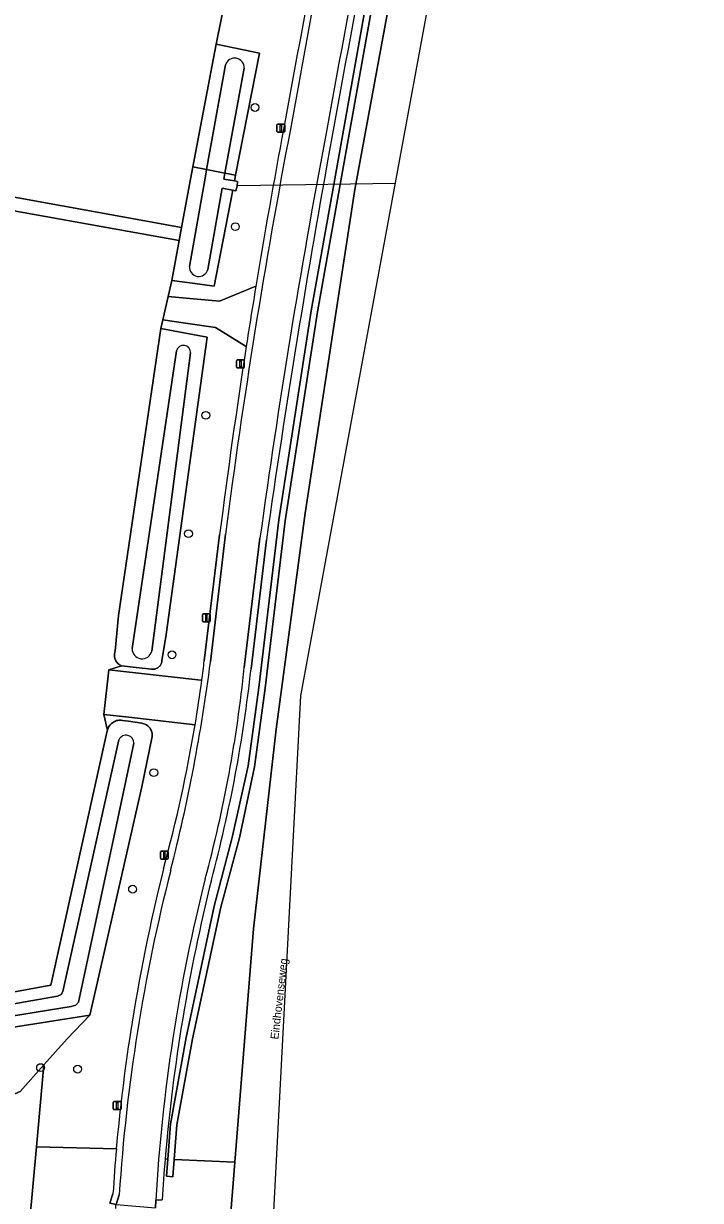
# Model space of a CAD drawing. Extents: x 161385 to 162589, y 388479 to 389756.
# Drawn here: x 162498.2 to 162582.9, y 389100.4 to 389247.5 of the extents above; entities that cross this region are included whole.
import ezdxf

# ---------------------------------------------------------------- set-up
doc = ezdxf.new("R2010")
doc.units = 0
for name, color, linetype in [('IMGEO_Berm_groen', 7, 'Continuous'), ('IMGEO_Berm_open', 7, 'Continuous'), ('IMGEO_Boom', 7, 'Continuous'), ('IMGEO_Bouwland', 7, 'Continuous'), ('IMGEO_Duiker', 7, 'Continuous'), ('IMGEO_Erf', 7, 'Continuous'), ('IMGEO_Fietspad_gesloten', 7, 'Continuous'), ('IMGEO_Grasland_overig', 7, 'Continuous'), ('IMGEO_Groenvoorziening', 7, 'Continuous'), ('IMGEO_Haag', 7, 'Continuous'), ('IMGEO_Lichtmast', 7, 'Continuous'), ('IMGEO_Loofbos', 7, 'Continuous'), ('IMGEO_Oever', 7, 'Continuous'), ('IMGEO_Openbare_ruimte_label', 7, 'Continuous'), ('IMGEO_Rijbaan_lokaal_open', 7, 'Continuous'), ('IMGEO_Rijbaan_regionaal_gesloten', 7, 'Continuous'), ('IMGEO_Verkeerseiland_groen', 7, 'Continuous'), ('IMGEO_Waterloop', 7, 'Continuous')]:
    doc.layers.add(name, color=color, linetype=linetype)

msp = doc.modelspace()

# ---------------------------------------------------------------- linework, layer by layer
at = {"layer": 'IMGEO_Berm_groen'}
for points in [[(162515.95, 389105.58), (162516.29, 389105.55), (162516.61, 389109.92), (162518.58, 389120.76), (162522.08, 389137.16), (162524.35, 389145.75), (162526.33, 389154.68), (162527.69, 389164.49), (162530.19, 389185.45), (162534.23, 389211.56), (162537.05, 389227.35), (162541.11, 389250.07)], [(162541.89, 389249.93), (162537.86, 389227.36), (162535.02, 389211.43), (162530.98, 389185.34), (162528.48, 389164.39), (162527.13, 389154.56), (162525.27, 389145.69), (162522.92, 389137.04), (162519.37, 389120.59), (162517.41, 389109.82), (162517.09, 389105.51), (162524.67, 389105.18), (162527.01, 389134.31), (162529.83, 389159.28), (162533.46, 389186.29), (162539.7, 389226.74), (162539.82, 389227.39), (162543.99, 389250)], [(162528.63, 389182.97), (162526.7, 389166.82)]]:
    msp.add_lwpolyline(points, dxfattribs=at)
for centre, radius, start, end in [((165430.74, 388709.98), 2940.85, 168.58464, 169.75115), ((163865.58, 388991.1), 1350.65, 169.67296, 171.83337), ((162353.56, 389185.73), 174.17, 344.9225, 353.7664), ((162738.94, 389086.46), 223.81, 166.0456, 175.0996)]:
    msp.add_arc(centre, radius, start, end, dxfattribs=at)
at = {"layer": 'IMGEO_Berm_open'}
for points in [[(162522.77, 389183.57), (162520.84, 389167.84)], [(162521.64, 389167.68), (162523.51, 389183.65)], [(162527.82, 389183.14), (162525.85, 389166.98)], [(162526.7, 389166.82), (162528.63, 389182.97)], [(162509.42, 389101.22), (162509.03, 389100.04), (162509.81, 389099.87), (162510.21, 389101.09)], [(162514.77, 389100.42), (162515.57, 389100.47)]]:
    msp.add_lwpolyline(points, dxfattribs=at)
for centre, radius, start, end in [((166558.63, 388497.78), 4094.64, 168.80107, 169.63564), ((165549.5, 388690.44), 3066.49, 168.66946, 169.78423), ((165801.81, 388642.75), 3318.76, 168.71278, 169.74959), ((165430.74, 388709.98), 2940.85, 168.58464, 169.75115), ((163380.67, 389072.21), 864.38, 169.19171, 172.59244), ((163383.98, 389073.51), 868.22, 169.3186, 170.64564), ((163529.83, 389045.24), 1011.46, 169.28293, 172.16365), ((163865.58, 388991.1), 1350.65, 169.67296, 171.83337), ((163357.31, 389077.87), 841.2, 170.64276, 171.16184), ((163371.45, 389075.44), 855.54, 171.14652, 172.73911), ((162300.78, 389196.46), 222.72, 345.7416, 352.5741), ((162337.16, 389189.91), 185.01, 352.3841, 353.1464), ((162361.08, 389183.83), 165.63, 344.8832, 354.1641), ((162353.56, 389185.73), 174.17, 344.9225, 353.7664), ((162340.51, 389189.55), 181.64, 350.5844, 352.3561), ((162342.8, 389189.17), 179.31, 344.6948, 350.5867), ((162731.04, 389086.79), 221.29, 165.6569, 176.2937), ((162735.65, 389086.74), 226.69, 165.9351, 171.2124), ((162729.97, 389087.83), 215.56, 165.8212, 176.6524), ((162738.94, 389086.46), 223.81, 166.0456, 175.0996), ((162735.42, 389086.75), 226.47, 171.2044, 174.9096), ((162735.89, 389086.69), 226.93, 174.9056, 176.3297), ((162733.03, 389086.87), 217.88, 175.074, 176.4218)]:
    msp.add_arc(centre, radius, start, end, dxfattribs=at)
at = {"layer": 'IMGEO_Boom'}
for centre in [(162527.19, 389236.99), (162524.74, 389222.09), (162521.05, 389198.52), (162518.88, 389183.72), (162516.81, 389168.58), (162514.53, 389153.85), (162511.88, 389139.28), (162500.37, 389116.98), (162505, 389116.79)]:
    msp.add_circle(centre, 0.489, dxfattribs=at)
at = {"layer": 'IMGEO_Bouwland'}
msp.add_lwpolyline([(162365.69, 389304.53), (162378.86, 389305.21), (162381.46, 389305.34), (162386.58, 389305.3), (162392.87, 389304.96), (162400.44, 389304.98), (162407.4, 389305.15), (162413.86, 389305.32), (162420.57, 389304.98), (162428.12, 389304.98), (162438.44, 389304.9), (162451.55, 389304.33), (162457.77, 389232.9), (162518.01, 389222.01), (162519.26, 389228.69), (162519.43, 389229.57), (162522.32, 389244.9), (162523.68, 389251.54), (162528.42, 389274.72), (162532.91, 389298.77), (162450.78, 389315.08), (162458.14, 389368.42)], dxfattribs=at)
at = {"layer": 'IMGEO_Duiker'}
msp.add_lwpolyline([(162525.04, 389227.23), (162544.78, 389227.55)], dxfattribs=at)
at = {"layer": 'IMGEO_Erf'}
msp.add_lwpolyline([(162464.29, 389120.39), (162501.65, 389127.29), (162508.71, 389159.07), (162508.73, 389159.13), (162508.3, 389161.12), (162508.89, 389166.7), (162510.49, 389167.21), (162510.46, 389167.22), (162510.35, 389167.27), (162510.24, 389167.34), (162510.14, 389167.42), (162510.04, 389167.51), (162509.95, 389167.6), (162509.87, 389167.7), (162509.8, 389167.81), (162509.74, 389167.92), (162509.69, 389168.04), (162509.66, 389168.17), (162509.63, 389168.29), (162509.61, 389168.42), (162509.61, 389168.55), (162509.62, 389168.68), (162509.64, 389168.81), (162509.67, 389168.93), (162509.71, 389169.06), (162510.13, 389173.5), (162515.4, 389209.36), (162515.66, 389210.47), (162516.35, 389213.36), (162516.77, 389215.38), (162517.7, 389220.36), (162461.43, 389230.46)], dxfattribs=at)
at = {"layer": 'IMGEO_Fietspad_gesloten'}
for points in [[(162523.51, 389183.65), (162521.64, 389167.68)], [(162525.85, 389166.98), (162527.82, 389183.14)], [(162510.21, 389101.09), (162509.81, 389099.87), (162514.74, 389099.44), (162514.77, 389100.42)]]:
    msp.add_lwpolyline(points, dxfattribs=at)
for centre, radius, start, end in [((165549.5, 388690.44), 3066.49, 168.66946, 169.78423), ((165801.81, 388642.75), 3318.76, 168.71278, 169.74959), ((163380.67, 389072.21), 864.38, 169.19171, 172.59244), ((163529.83, 389045.24), 1011.46, 169.28293, 172.16365), ((162300.78, 389196.46), 222.72, 345.7416, 352.5741), ((162361.08, 389183.83), 165.63, 344.8832, 354.1641), ((162731.04, 389086.79), 221.29, 165.6569, 176.2937), ((162729.97, 389087.83), 215.56, 165.8212, 176.6524)]:
    msp.add_arc(centre, radius, start, end, dxfattribs=at)
at = {"layer": 'IMGEO_Grasland_overig'}
msp.add_lwpolyline([(162452.04, 389250), (162454.75, 389231.66), (162461.43, 389230.46), (162517.7, 389220.36), (162518.01, 389222.01), (162457.77, 389232.9), (162451.55, 389304.33)], dxfattribs=at)
at = {"layer": 'IMGEO_Groenvoorziening'}
for points in [[(162523.68, 389251.54), (162522.32, 389244.9), (162524.75, 389244.4), (162527.74, 389243.79), (162524.77, 389228.54), (162524.66, 389228.01), (162524.63, 389227.82), (162525, 389227.76), (162524.96, 389227.16), (162524.81, 389226.56), (162524.4, 389226.64), (162524.36, 389226.43), (162522.07, 389214.66), (162519.37, 389215.03), (162516.77, 389215.38), (162516.35, 389213.36), (162519.05, 389213.13), (162522.77, 389212.8), (162527.3, 389214.64)], [(162541.11, 389250.07), (162537.05, 389227.35), (162534.23, 389211.56), (162530.19, 389185.45), (162527.69, 389164.49), (162526.33, 389154.68), (162524.35, 389145.75), (162522.08, 389137.16), (162518.58, 389120.76), (162516.61, 389109.92), (162516.29, 389105.55), (162516.13, 389103.4), (162516.93, 389103.34), (162517.09, 389105.51), (162517.41, 389109.82), (162519.37, 389120.59), (162522.92, 389137.04), (162525.27, 389145.69), (162527.13, 389154.56), (162528.48, 389164.39), (162530.98, 389185.34), (162535.02, 389211.43), (162537.86, 389227.36), (162541.89, 389249.93)], [(162526.1, 389207.11), (162522.25, 389209.48), (162518.52, 389210.04), (162515.66, 389210.47), (162515.4, 389209.36), (162518.31, 389208.83), (162521.21, 389208.29), (162516.09, 389171.11), (162515.54, 389167.83), (162515.53, 389167.76), (162515.52, 389167.66), (162515.49, 389167.57), (162515.46, 389167.47), (162515.42, 389167.38), (162515.37, 389167.29), (162515.31, 389167.21), (162515.25, 389167.14), (162515.18, 389167.06), (162515.1, 389167), (162515.02, 389166.94), (162514.94, 389166.89), (162514.85, 389166.85), (162514.75, 389166.81), (162514.65, 389166.79), (162514.55, 389166.77), (162514.46, 389166.77), (162514.36, 389166.77), (162514.26, 389166.78), (162512.33, 389166.99), (162510.49, 389167.21), (162508.89, 389166.7), (162512.24, 389166.33), (162520.41, 389165.4), (162520.53, 389165.39)], [(162520.84, 389167.84), (162522.77, 389183.57)], [(162519.7, 389159.84), (162511.42, 389160.77), (162508.3, 389161.12), (162508.73, 389159.13), (162508.76, 389159.27), (162508.82, 389159.41), (162508.88, 389159.54), (162508.95, 389159.67), (162509.04, 389159.79), (162509.14, 389159.9), (162509.24, 389160), (162509.36, 389160.09), (162509.48, 389160.17), (162509.61, 389160.24), (162509.74, 389160.3), (162509.88, 389160.35), (162510.02, 389160.38), (162510.17, 389160.4), (162510.31, 389160.41), (162510.46, 389160.4), (162510.6, 389160.38), (162511.35, 389160.28), (162513.04, 389160.03), (162513.16, 389160.01), (162513.29, 389159.97), (162513.42, 389159.92), (162513.55, 389159.86), (162513.66, 389159.79), (162513.77, 389159.71), (162513.88, 389159.62), (162513.97, 389159.52), (162514.06, 389159.41), (162514.13, 389159.3), (162514.2, 389159.17), (162514.25, 389159.05), (162514.29, 389158.92), (162514.32, 389158.79), (162514.34, 389158.65), (162514.35, 389158.51), (162514.34, 389158.38), (162513.03, 389152.06), (162507.36, 389127.14), (162506.53, 389123.52), (162503.71, 389120.57), (162500.78, 389117.31), (162499.85, 389107.07), (162509.85, 389106.84)], [(162509.85, 389106.84), (162499.85, 389107.07), (162498.96, 389097.09), (162500, 389096.93), (162503.05, 389096.67), (162504.14, 389096.81), (162506.22, 389096.8)], [(162509.79, 389099.38), (162509.8, 389099.73), (162509.81, 389099.87), (162509.03, 389100.04), (162509.42, 389101.22)]]:
    msp.add_lwpolyline(points, dxfattribs=at)
msp.add_lwpolyline([(162500.78, 389117.31), (162497.83, 389114.01), (162491.39, 389111.2), (162486.6, 389105.87), (162485.73, 389102.19), (162485.57, 389100.86), (162490.55, 389099.01), (162491.45, 389098.72), (162492.35, 389098.43), (162497.21, 389097.36), (162498.96, 389097.09), (162499.85, 389107.07)], close=True, dxfattribs=at)
for centre, radius, start, end in [((166558.63, 388497.78), 4094.64, 168.80107, 169.63564), ((163383.98, 389073.51), 868.22, 169.3186, 170.64564), ((163371.45, 389075.44), 855.54, 171.14652, 172.73911), ((162337.16, 389189.91), 185.01, 352.3841, 353.1464), ((162342.8, 389189.17), 179.31, 344.6948, 350.5867), ((162735.65, 389086.74), 226.69, 165.9351, 171.2124), ((162735.42, 389086.75), 226.47, 171.2044, 174.9096), ((162735.89, 389086.69), 226.93, 174.9056, 176.3297)]:
    msp.add_arc(centre, radius, start, end, dxfattribs=at)
at = {"layer": 'IMGEO_Haag'}
msp.add_lwpolyline([(162541.11, 389250.07), (162537.05, 389227.35), (162534.23, 389211.56), (162530.19, 389185.45), (162527.69, 389164.49), (162526.33, 389154.68), (162524.35, 389145.75), (162522.08, 389137.16), (162518.58, 389120.76), (162516.61, 389109.92), (162516.29, 389105.55), (162516.13, 389103.4), (162516.93, 389103.34), (162517.09, 389105.51), (162517.41, 389109.82), (162519.37, 389120.59), (162522.92, 389137.04), (162525.27, 389145.69), (162527.13, 389154.56), (162528.48, 389164.39), (162530.98, 389185.34), (162535.02, 389211.43), (162537.86, 389227.36), (162541.89, 389249.93)], dxfattribs=at)
at = {"layer": 'IMGEO_Lichtmast'}
for p, q in [((162529.94, 389234.01), (162529.94, 389234.81)), ((162529.94, 389234.81), (162529.94, 389234.01)), ((162530.04, 389234.91), (162530.83, 389234.91)), ((162530.83, 389234.91), (162530.04, 389234.91)), ((162530.83, 389233.91), (162530.04, 389233.91)), ((162530.04, 389233.91), (162530.83, 389233.91)), ((162530.93, 389234.81), (162530.93, 389234.01)), ((162530.93, 389234.01), (162530.93, 389234.81)), ((162524.88, 389204.54), (162524.88, 389205.34)), ((162524.88, 389205.34), (162524.88, 389204.54)), ((162524.98, 389205.44), (162525.76, 389205.44)), ((162525.76, 389205.44), (162524.98, 389205.44)), ((162525.76, 389204.44), (162524.98, 389204.44)), ((162524.98, 389204.44), (162525.76, 389204.44)), ((162525.86, 389205.34), (162525.86, 389204.54)), ((162525.86, 389204.54), (162525.86, 389205.34)), ((162520.61, 389172.8), (162520.61, 389173.6)), ((162520.61, 389173.6), (162520.61, 389172.8)), ((162520.71, 389173.7), (162521.5, 389173.7)), ((162521.5, 389173.7), (162520.71, 389173.7)), ((162521.6, 389173.6), (162521.6, 389172.8)), ((162521.6, 389172.8), (162521.6, 389173.6)), ((162521.5, 389172.7), (162520.71, 389172.7)), ((162520.71, 389172.7), (162521.5, 389172.7)), ((162515.36, 389143.14), (162515.36, 389143.94)), ((162515.36, 389143.94), (162515.36, 389143.14)), ((162515.46, 389144.04), (162516.25, 389144.04)), ((162516.25, 389144.04), (162515.46, 389144.04)), ((162516.35, 389143.94), (162516.35, 389143.14)), ((162516.35, 389143.14), (162516.35, 389143.94)), ((162516.25, 389143.04), (162515.46, 389143.04)), ((162515.46, 389143.04), (162516.25, 389143.04)), ((162509.46, 389111.83), (162509.46, 389112.63)), ((162509.46, 389112.63), (162509.46, 389111.83)), ((162509.56, 389112.73), (162510.35, 389112.73)), ((162510.35, 389112.73), (162509.56, 389112.73)), ((162510.35, 389111.73), (162509.56, 389111.73)), ((162509.56, 389111.73), (162510.35, 389111.73)), ((162510.45, 389112.63), (162510.45, 389111.83)), ((162510.45, 389111.83), (162510.45, 389112.63))]:
    msp.add_line(p, q, dxfattribs=at)
for points in [[(162530.36, 389234.78), (162530.51, 389234.78), (162530.51, 389234.03), (162530.36, 389234.03), (162530.36, 389234.78)], [(162525.29, 389205.31), (162525.45, 389205.31), (162525.45, 389204.56), (162525.29, 389204.56), (162525.29, 389205.31)], [(162521.03, 389173.57), (162521.18, 389173.57), (162521.18, 389172.82), (162521.03, 389172.82), (162521.03, 389173.57)], [(162515.78, 389143.92), (162515.93, 389143.92), (162515.93, 389143.17), (162515.78, 389143.17), (162515.78, 389143.92)], [(162509.88, 389112.6), (162510.03, 389112.6), (162510.03, 389111.85), (162509.88, 389111.85), (162509.88, 389112.6)]]:
    msp.add_lwpolyline(points, dxfattribs=at)
for centre, start, end in [((162530.04, 389234.81), 90, 180), ((162530.04, 389234.81), 90, 180), ((162530.04, 389234.01), 180, 270), ((162530.04, 389234.01), 180, 270), ((162530.83, 389234.81), 0, 90), ((162530.83, 389234.81), 360, 90), ((162530.83, 389234.01), 270, 0), ((162530.83, 389234.01), 270, 0), ((162524.98, 389205.34), 90, 180), ((162524.98, 389205.34), 90, 180), ((162524.98, 389204.54), 180, 270), ((162524.98, 389204.54), 180, 270), ((162525.76, 389205.34), 0, 90), ((162525.76, 389205.34), 360, 90), ((162525.76, 389204.54), 270, 0), ((162525.76, 389204.54), 270, 0), ((162520.71, 389173.6), 90, 180), ((162520.71, 389173.6), 90, 180), ((162521.5, 389173.6), 0, 90), ((162521.5, 389173.6), 360, 90), ((162520.71, 389172.8), 180, 270), ((162520.71, 389172.8), 180, 270), ((162521.5, 389172.8), 270, 0), ((162521.5, 389172.8), 270, 0), ((162515.46, 389143.94), 90, 180), ((162515.46, 389143.94), 90, 180), ((162516.25, 389143.94), 0, 90), ((162516.25, 389143.94), 360, 90), ((162515.46, 389143.14), 180, 270), ((162515.46, 389143.14), 180, 270), ((162516.25, 389143.14), 270, 0), ((162516.25, 389143.14), 270, 0), ((162509.56, 389112.63), 90, 180), ((162509.56, 389112.63), 90, 180), ((162509.56, 389111.83), 180, 270), ((162509.56, 389111.83), 180, 270), ((162510.35, 389112.63), 0, 90), ((162510.35, 389112.63), 360, 90), ((162510.35, 389111.83), 270, 0), ((162510.35, 389111.83), 270, 0)]:
    msp.add_arc(centre, 0.1, start, end, dxfattribs=at)
at = {"layer": 'IMGEO_Loofbos'}
msp.add_lwpolyline([(162503.71, 389120.57), (162506.53, 389123.52), (162501.24, 389122.69), (162477.09, 389118.89), (162464.99, 389116.84), (162464.67, 389118.46), (162464.29, 389120.39), (162462.23, 389120), (162462.59, 389118.05), (162462.88, 389116.48), (162442.25, 389112.99), (162443.13, 389111.82), (162447.72, 389111.92), (162452.3, 389111.62), (162456.83, 389110.91), (162461.29, 389109.79), (162465.62, 389108.29), (162485.57, 389100.86), (162485.73, 389102.19), (162486.6, 389105.87), (162491.39, 389111.2), (162497.83, 389114.01), (162500.78, 389117.31)], close=True, dxfattribs=at)
at = {"layer": 'IMGEO_Oever'}
for points in [[(162525.84, 389241.91), (162523.43, 389228.8), (162524.77, 389228.54), (162527.74, 389243.79), (162524.75, 389244.4), (162522.32, 389244.9), (162519.43, 389229.57)], [(162519.43, 389229.57), (162521.14, 389229.24), (162523.5, 389242.32)], [(162521.14, 389229.24), (162519.43, 389229.57), (162519.26, 389228.69), (162518.01, 389222.01), (162517.7, 389220.36), (162516.77, 389215.38), (162519.37, 389215.03), (162522.07, 389214.66), (162524.36, 389226.43), (162524.4, 389226.64), (162523.08, 389226.89), (162521.31, 389216.74)], [(162519, 389217.13), (162520.99, 389228.41), (162521.14, 389229.24)], [(162511.83, 389169.36), (162517.39, 389206.56)], [(162519.12, 389206.32), (162514.28, 389169.04)], [(162477.09, 389118.89), (162501.24, 389122.69), (162506.53, 389123.52), (162507.36, 389127.14), (162513.03, 389152.06), (162514.34, 389158.38), (162514.35, 389158.51), (162514.34, 389158.65), (162514.32, 389158.79), (162514.29, 389158.92), (162514.25, 389159.05), (162514.2, 389159.17), (162514.13, 389159.3), (162514.06, 389159.41), (162513.97, 389159.52), (162513.88, 389159.62), (162513.77, 389159.71), (162513.66, 389159.79), (162513.55, 389159.86), (162513.42, 389159.92), (162513.29, 389159.97), (162513.16, 389160.01), (162513.04, 389160.03), (162511.35, 389160.28), (162510.6, 389160.38), (162510.46, 389160.4), (162510.31, 389160.41), (162510.17, 389160.4), (162510.02, 389160.38), (162509.88, 389160.35), (162509.74, 389160.3), (162509.61, 389160.24), (162509.48, 389160.17), (162509.36, 389160.09), (162509.24, 389160), (162509.14, 389159.9), (162509.04, 389159.79), (162508.95, 389159.67), (162508.88, 389159.54), (162508.82, 389159.41), (162508.76, 389159.27), (162508.73, 389159.13), (162508.71, 389159.07), (162501.65, 389127.29), (162464.29, 389120.39)], [(162465.56, 389119.47), (162502.48, 389125.91), (162502.94, 389126.12), (162503.14, 389126.51), (162510.18, 389157.95)], [(162512.05, 389157.52), (162509.73, 389146.76), (162505.11, 389125.18), (162504.78, 389124.79), (162504.18, 389124.6), (162488.97, 389122.14), (162465.85, 389118.02), (162465.56, 389119.47)]]:
    msp.add_lwpolyline(points, dxfattribs=at)
for points in [[(162524.77, 389228.54), (162523.43, 389228.8), (162523.28, 389228.03), (162524.63, 389227.82), (162524.66, 389228.01)], [(162521.21, 389208.29), (162518.31, 389208.83), (162515.4, 389209.36), (162510.13, 389173.5), (162509.71, 389169.06), (162509.67, 389168.93), (162509.64, 389168.81), (162509.62, 389168.68), (162509.61, 389168.55), (162509.61, 389168.42), (162509.63, 389168.29), (162509.66, 389168.17), (162509.69, 389168.04), (162509.74, 389167.92), (162509.8, 389167.81), (162509.87, 389167.7), (162509.95, 389167.6), (162510.04, 389167.51), (162510.14, 389167.42), (162510.24, 389167.34), (162510.35, 389167.27), (162510.46, 389167.22), (162510.49, 389167.21), (162512.33, 389166.99), (162514.26, 389166.78), (162514.36, 389166.77), (162514.46, 389166.77), (162514.55, 389166.77), (162514.65, 389166.79), (162514.75, 389166.81), (162514.85, 389166.85), (162514.94, 389166.89), (162515.02, 389166.94), (162515.1, 389167), (162515.18, 389167.06), (162515.25, 389167.14), (162515.31, 389167.21), (162515.37, 389167.29), (162515.42, 389167.38), (162515.46, 389167.47), (162515.49, 389167.57), (162515.52, 389167.66), (162515.53, 389167.76), (162515.54, 389167.83), (162516.09, 389171.11)]]:
    msp.add_lwpolyline(points, close=True, dxfattribs=at)
for centre, radius, start, end in [((162524.65, 389241.96), 1.2, 357.2372, 162.8474), ((162520.17, 389217.04), 1.17, 175.6482, 345.1451), ((162518.24, 389206.38), 0.875, 355.8359, 168.0896), ((162513.07, 389169.32), 1.24, 177.9953, 346.9475), ((162511.07, 389157.56), 0.976, 357.8213, 156.2073)]:
    msp.add_arc(centre, radius, start, end, dxfattribs=at)
at = {"layer": 'IMGEO_Rijbaan_lokaal_open'}
for points in [[(162527.3, 389214.64), (162522.77, 389212.8), (162519.05, 389213.13), (162516.35, 389213.36), (162515.66, 389210.47), (162518.52, 389210.04), (162522.25, 389209.48), (162526.1, 389207.11)], [(162520.53, 389165.39), (162520.41, 389165.4), (162512.24, 389166.33), (162508.89, 389166.7), (162508.3, 389161.12), (162511.42, 389160.77), (162519.7, 389159.84)]]:
    msp.add_lwpolyline(points, dxfattribs=at)
for centre, radius, start, end in [((163357.31, 389077.87), 841.2, 170.64276, 171.16184), ((162340.51, 389189.55), 181.64, 350.5844, 352.3561)]:
    msp.add_arc(centre, radius, start, end, dxfattribs=at)
at = {"layer": 'IMGEO_Rijbaan_regionaal_gesloten'}
for points in [[(162529.37, 389095.84), (162532.95, 389163.46), (162561.1, 389315.91), (162582.93, 389467.23)], [(162566.28, 389369.56), (162559.5, 389330.64), (162553.24, 389299.28), (162543.99, 389250), (162539.82, 389227.39), (162539.7, 389226.74), (162533.46, 389186.29), (162529.83, 389159.28), (162527.01, 389134.31), (162524.67, 389105.18), (162523.87, 389095.21)]]:
    msp.add_lwpolyline(points, dxfattribs=at)
at = {"layer": 'IMGEO_Verkeerseiland_groen'}
for points in [[(162524.67, 389105.18), (162517.09, 389105.51), (162516.93, 389103.34), (162516.13, 389103.4), (162516.29, 389105.55), (162515.95, 389105.58)], [(162518.47, 389095.53), (162523.87, 389095.21), (162524.67, 389105.18)], [(162515.57, 389100.47), (162514.77, 389100.42), (162514.74, 389099.44)]]:
    msp.add_lwpolyline(points, dxfattribs=at)
msp.add_arc((162733.03, 389086.87), 217.88, 175.074, 176.4218, dxfattribs=at)
at = {"layer": 'IMGEO_Waterloop'}
for points in [[(162523.5, 389242.32), (162521.14, 389229.24)], [(162521.14, 389229.24), (162523.43, 389228.8), (162525.84, 389241.91)], [(162523.08, 389226.89), (162524.4, 389226.64), (162524.81, 389226.56), (162524.96, 389227.16), (162525, 389227.76), (162524.63, 389227.82), (162523.28, 389228.03), (162523.43, 389228.8), (162521.14, 389229.24), (162520.99, 389228.41), (162519, 389217.13)], [(162521.31, 389216.74), (162523.08, 389226.89)], [(162517.39, 389206.56), (162511.83, 389169.36)], [(162514.28, 389169.04), (162519.12, 389206.32)], [(162510.18, 389157.95), (162503.14, 389126.51), (162502.94, 389126.12), (162502.48, 389125.91), (162465.56, 389119.47), (162465.85, 389118.02), (162488.97, 389122.14), (162504.18, 389124.6), (162504.78, 389124.79), (162505.11, 389125.18), (162509.73, 389146.76), (162512.05, 389157.52)]]:
    msp.add_lwpolyline(points, dxfattribs=at)
for centre, radius, start, end in [((162524.65, 389241.96), 1.2, 357.2372, 162.8474), ((162520.17, 389217.04), 1.17, 175.6482, 345.1451), ((162518.24, 389206.38), 0.875, 355.8359, 168.0896), ((162513.07, 389169.32), 1.24, 177.9953, 346.9475), ((162511.07, 389157.56), 0.976, 357.8213, 156.2073)]:
    msp.add_arc(centre, radius, start, end, dxfattribs=at)

# ---------------------------------------------------------------- texts
at = {"layer": 'IMGEO_Openbare_ruimte_label'}
msp.add_text('Eindhovenseweg', height=1, rotation=83.394, dxfattribs=at).set_placement((162530.11, 389120.46))

doc.saveas('drawing.dxf')
